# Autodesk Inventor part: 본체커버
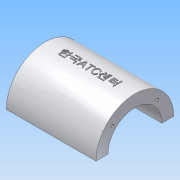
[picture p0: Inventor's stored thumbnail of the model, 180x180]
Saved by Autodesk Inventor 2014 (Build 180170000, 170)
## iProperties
Created: 2015-12
Part Number: 본체커버
Material: 알루미늄 6061
Document SubType Name: Modeling
Designer: mduedu
Density: 2.71 g/cm^3
Mass: 174.994 g
Surface Area: 167.085 cm^2
Volume: 64.5736 cm^3
Appearance: 알루미늄 - 평지
Author: mduedu
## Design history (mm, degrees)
sketch "스케치1"
  geometry: L1 (45, 40)-(-45, 40); L2 (-45, 40)-(-45, -40); L3 (-45, -40)-(45, -40); L4 (45, -40)-(45, 40); L5 (45, 40)-(-45, -40); L6 (-45, 40)-(45, -40); 1 further point
  constraints: 12 end point, 2 midpoint, 2 parallel, 1 horizontal, 1 perpendicular
  dimensions: "d0" = 90 distance of L2.end L3.end; "d2" = 80 distance of L1.end L2.end
extrude "돌출1" new body sketch "스케치1" distance "d3" = 10; taper "d4" = 0 deg
sketch "스케치2"
  geometry: L1 (0, 40)-(0, -40) reference; C1 r 32.5 at (80, 0); 1 further point
  constraints: 1 centre point
  dimensions: "d5" = 65 diameter of C1; "d6" = 80 distance from line of C1.centre L1
extrude "돌출2" join sketch "스케치2" stored distance "d7" = 75; taper "d8" = 0 deg
sketch "스케치3"
  geometry: L1 (-27.5, -20)-(27.5, -20); L2 (27.5, -20)-(27.5, 20); L3 (27.5, 20)-(-27.5, 20); L4 (-27.5, 20)-(-27.5, -20); L5 (-27.5, -20)-(27.5, 20); L6 (27.5, -20)-(-27.5, 20); 1 further point
  constraints: 12 end point, 2 midpoint, 2 parallel, 1 horizontal, 1 perpendicular
  dimensions: "d9" = 55 distance of L2.end L3.end; "d11" = 40 distance of L1.end L2.end
extrude "돌출3" new body sketch "스케치3" stored distance "d12" = 75; taper "d13" = 0 deg
fillet "모깎기1"
fillet "모깎기2"
feature "결합1"
  node "솔리드2"
fillet "모깎기3" dims "d14" = 10
sketch "스케치4"
  geometry: L1 (-37.5, 47.5)-(37.5, 47.5) reference; L2 (35, 10)-(45, 10) reference; L3 (32.5, 47.5)-(40, 10); L4 (37.5, 47.5)-(37.5, 112.5) reference; L5 (45, 10)-(45, 0) reference; 1 further point
  constraints: 2 end point, 1 midpoint, 1 point on line
  dimensions: "d15" = 5 distance from line of L3.start L4; "d16" = 5 distance from line of L3.end L5
sketch "스케치5"
  geometry: L1 (10, 40)-(10, 30) reference; L2 (10, 35)-(56.569, 22.522); L3 (0, 40)-(10, 40) reference; 2 further points
  constraints: 2 end point, 1 midpoint, 2 other
  dimensions: "d17" = 5 distance from line of L2.start L3; "d18" = 15 deg angle of L2 L3
feature "리브1" dims "d19" = 1, "d20" = 6, "d21" = 0, "d22" = 0, "d23" = 1, "d24" = 1
feature "리브2" dims "d25" = 1, "d26" = 6, "d27" = 0, "d28" = 0, "d29" = 1, "d30" = 1
fillet "모깎기4" dims "d31" = 2
fillet "모깎기5" dims "d32" = 2
fillet "모깎기6" dims "d33" = 2
sketch "스케치6"
  geometry: A1 r 10 centre (-35, 30) between (-35, 40) and (-45, 30) reference; A2 r 10 centre (35, 30) between (45, 30) and (35, 40) reference; A3 r 10 centre (35, -30) between (35, -40) and (45, -30) reference; A4 r 10 centre (-35, -30) between (-45, -30) and (-35, -40) reference; 5 further points
  constraints: 4 coincident
hole "구멍1" sketch "스케치6" at (-35, 30), (35, 30), (35, -30), (-35, -30) diameter "d34" = 7; stored, may be unused: countersink angle "d38" = 90 deg, drill point angle "d40" = 118 deg; dims "d35" = 6, "d36" = 12, "d37" = 3, "d39" = 8
fillet "모깎기7" dims "d41" = 2
hole "구멍2" diameter "d44" = 45; stored, may be unused: countersink angle "d48" = 90 deg, drill point angle "d50" = 118 deg; dims "d42" = 10, "d43" = 10, "d45" = 6, "d46" = 4, "d47" = 2, "d49" = 8
sketch "스케치7" dims "d52" = 26.5
  geometry: L1 (0, 0)-(32.5, 0); L2 (0, 0)-(22.981, 22.981); A1 r 32.5 centre (0, 0) between (32.5, 0) and (22.981, 22.981) reference; 3 further points
  constraints: 4 end point, 2 point on circle, 1 coincident, 1 horizontal, 1 point on line, 3 other
  dimensions: "d51" = 45 deg angle of L2 L1
hole "구멍3" sketch "스케치7" at (18.738, 18.738) diameter "d54" = 2.459; stored, may be unused: countersink angle "d58" = 90 deg, drill point angle "d60" = 118 deg; dims "d55" = 8, "d56" = 4, "d57" = 2, "d59" = 10
sketch "스케치13"
  geometry: L1 (-45, 80)-(105, 80); L2 (105, 80)-(105, -30); L3 (105, -30)-(-45, -30); L4 (-45, -30)-(-45, 80); L5 (0, 0)-(60, 0) reference; C1 r 32.5 at (30, 80) reference; 1 further point
  constraints: 8 end point, 2 parallel, 1 coincident, 1 horizontal, 1 midpoint, 1 perpendicular
  dimensions: "d99" = 30 distance between parallel lines of L3 L5; "d126" = 150 distance between parallel lines of L2 L4
extrude "돌출8" cut sketch "스케치13" stored distance "d97" = 10; taper "d98" = 0 deg
node "작업 평면2"
sketch "스케치14"
  geometry: 2 further points
  constraints: 1 coincident, 1 other
feature "엠보싱1" sketch "스케치14" dims "d102" = 0.5, "d103" = 0
sketch "스케치18"
  geometry: L1 (0, -10)-(0, 0) reference; L2 (75, 0)-(75, -10) reference; L3 (0, -5)-(75, -5); C1 r 1.5 at (13, -5); 1 further point
  constraints: 2 end point, 2 midpoint, 1 centre point, 1 point on line
  dimensions: "d127" = 3 diameter of C1; "d128" = 13 distance from line of L1 C1.centre
extrude "돌출9" cut sketch "스케치18" distance "d129" = 2; taper "d130" = 0 deg
chamfer "모따기2" distance "d131" = 0.5; stored, may be unused: second distance "d132" = 2, angle "d133" = 45 deg
fillet "모깎기12" dims "d134" = 0.1
node "솔리드1"
mirror "대칭1"
mirror "대칭2"
pattern_circular "원형 패턴1" dims angle "d62" = 360 deg
mirror "대칭3"
mirror "대칭5"
mirror "대칭6"
